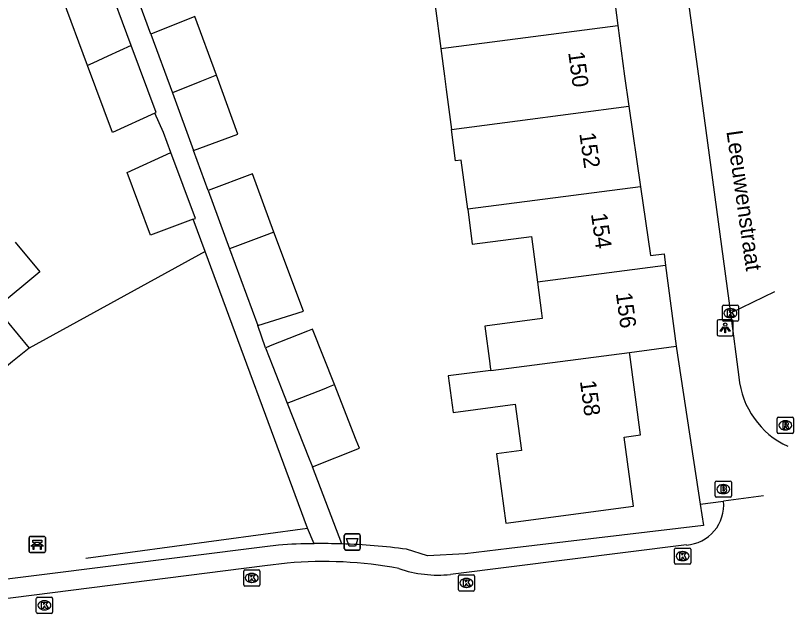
# Model space of a CAD drawing. Extents: x 163150 to 163546, y 380933 to 381635.
# Drawn here: x 163484.57 to 163532.74, y 380966.75 to 381003.76 of the extents above; entities that cross this region are included whole.
import ezdxf

# ---------------------------------------------------------------- set-up
doc = ezdxf.new("R2010")
doc.units = 0
for name, color, linetype in [('IMGEO_Afvalbak', 7, 'Continuous'), ('IMGEO_Bank', 7, 'Continuous'), ('IMGEO_Brandkraan', 7, 'Continuous'), ('IMGEO_Hek', 7, 'Continuous'), ('IMGEO_Kolk', 7, 'Continuous'), ('IMGEO_Lichtpunt', 7, 'Continuous'), ('IMGEO_Muur', 7, 'Continuous'), ('IMGEO_Openbare_ruimte_label', 7, 'Continuous'), ('IMGEO_Pand', 7, 'Continuous'), ('IMGEO_Pand_nummerreeks', 7, 'Continuous'), ('IMGEO_Rijbaan_lokaal_open', 7, 'Continuous'), ('IMGEO_Rioolput', 7, 'Continuous'), ('IMGEO_Voetpad_open', 7, 'Continuous')]:
    doc.layers.add(name, color=color, linetype=linetype)

msp = doc.modelspace()

# ---------------------------------------------------------------- linework, layer by layer
at = {"layer": 'IMGEO_Afvalbak'}
for p, q in [((163504.927, 380970.776), (163504.927, 380971.576)), ((163504.927, 380971.576), (163504.927, 380970.776)), ((163505.027, 380971.676), (163505.817, 380971.676)), ((163505.817, 380971.676), (163505.027, 380971.676)), ((163505.917, 380971.576), (163505.917, 380970.776)), ((163505.917, 380970.776), (163505.917, 380971.576)), ((163505.817, 380970.676), (163505.027, 380970.676)), ((163505.027, 380970.676), (163505.817, 380970.676))]:
    msp.add_line(p, q, dxfattribs=at)
msp.add_lwpolyline([(163505.07, 380971.39), (163505.774, 380971.39), (163505.625, 380970.92), (163505.219, 380970.92), (163505.07, 380971.39)], dxfattribs=at)
for centre, start, end in [((163505.027, 380971.576), 90, 180), ((163505.027, 380971.576), 90, 180), ((163505.817, 380971.576), 0, 90), ((163505.817, 380971.576), 360, 90), ((163505.027, 380970.776), 180, 270), ((163505.027, 380970.776), 180, 270), ((163505.817, 380970.776), 270, 0), ((163505.817, 380970.776), 270, 0)]:
    msp.add_arc(centre, 0.1, start, end, dxfattribs=at)
at = {"layer": 'IMGEO_Bank'}
for p, q in [((163485.487, 380971.517), (163486.328, 380971.517)), ((163486.328, 380971.517), (163485.487, 380971.517)), ((163485.412, 380970.592), (163485.412, 380971.433)), ((163485.412, 380971.433), (163485.412, 380970.592)), ((163485.721, 380971.023), (163485.721, 380971.129)), ((163485.765, 380971.129), (163485.765, 380971.023)), ((163486.053, 380971.135), (163485.771, 380971.135)), ((163485.771, 380971.017), (163486.053, 380971.017)), ((163486.059, 380971.023), (163486.059, 380971.129)), ((163486.103, 380971.129), (163486.103, 380971.023)), ((163486.412, 380971.442), (163486.412, 380970.601)), ((163486.412, 380970.601), (163486.412, 380971.442)), ((163486.109, 380970.915), (163485.716, 380970.915)), ((163486.337, 380970.517), (163485.496, 380970.517)), ((163485.496, 380970.517), (163486.337, 380970.517))]:
    msp.add_line(p, q, dxfattribs=at)
for points in [[(163485.659, 380970.915), (163485.517, 380970.915), (163485.629, 380971.017), (163485.715, 380971.017)], [(163485.715, 380971.135), (163485.629, 380971.135), (163485.629, 380971.296), (163486.192, 380971.296), (163486.192, 380971.135), (163486.109, 380971.135)], [(163486.109, 380971.017), (163486.192, 380971.017), (163486.304, 380970.915), (163486.165, 380970.915)], [(163485.709, 380970.908), (163485.709, 380970.701), (163485.666, 380970.701), (163485.666, 380970.908)], [(163486.159, 380970.908), (163486.159, 380970.701), (163486.115, 380970.701), (163486.115, 380970.908)]]:
    msp.add_lwpolyline(points, dxfattribs=at)
for centre, radius, start, end in [((163485.49, 380971.439), 0.0779, 92.4484, 184.2845), ((163485.49, 380971.439), 0.0779, 92.4484, 184.2845), ((163486.334, 380971.439), 0.0779, 2.4484, 94.2845), ((163486.334, 380971.439), 0.0779, 2.4484, 94.2845), ((163485.714, 380971.128), 0.00671, 2.8957, 87.1043), ((163485.714, 380971.024), 0.00671, 272.8957, 357.1043), ((163485.771, 380971.128), 0.00671, 92.8957, 177.1043), ((163485.771, 380971.024), 0.00671, 182.8957, 267.1043), ((163486.053, 380971.128), 0.00671, 2.8957, 87.1043), ((163486.053, 380971.024), 0.00671, 272.8957, 357.1043), ((163486.11, 380971.128), 0.00671, 92.8957, 177.1043), ((163486.11, 380971.024), 0.00671, 182.8957, 267.1043), ((163485.49, 380970.595), 0.0779, 182.4484, 274.2845), ((163485.49, 380970.595), 0.0779, 182.4484, 274.2845), ((163485.659, 380970.908), 0.00671, 2.8957, 87.1043), ((163485.716, 380970.908), 0.00671, 92.8957, 177.1043), ((163486.108, 380970.908), 0.00671, 2.8957, 87.1043), ((163486.165, 380970.908), 0.00671, 92.8957, 177.1043), ((163486.334, 380970.595), 0.0779, 272.4484, 4.2845), ((163486.334, 380970.595), 0.0779, 272.4484, 4.2845)]:
    msp.add_arc(centre, radius, start, end, dxfattribs=at)
at = {"layer": 'IMGEO_Brandkraan'}
for p, q in [((163527.898, 380974.021), (163527.898, 380974.873)), ((163527.973, 380974.947), (163528.825, 380974.947)), ((163528.899, 380974.873), (163528.899, 380974.021)), ((163528.386, 380974.727), (163528.411, 380974.727)), ((163528.825, 380973.947), (163527.973, 380973.947)), ((163528.409, 380974.167), (163528.384, 380974.167))]:
    msp.add_line(p, q, dxfattribs=at)
for points in [[(163527.898, 380974.021), (163527.898, 380974.873)], [(163527.973, 380974.947), (163528.825, 380974.947)], [(163528.899, 380974.873), (163528.899, 380974.021)], [(163528.246, 380974.647), (163528.246, 380974.247), (163528.459, 380974.247)], [(163528.477, 380974.647), (163528.246, 380974.647)], [(163528.425, 380974.566), (163528.371, 380974.566), (163528.371, 380974.49)], [(163528.371, 380974.49), (163528.424, 380974.49)], [(163528.433, 380974.414), (163528.371, 380974.414), (163528.371, 380974.333)], [(163528.825, 380973.947), (163527.973, 380973.947)], [(163528.371, 380974.333), (163528.433, 380974.333)]]:
    msp.add_lwpolyline(points, dxfattribs=at)
for centre, radius, start, end in [((163527.975, 380974.871), 0.0765, 91.552, 178.448), ((163527.975, 380974.871), 0.0765, 91.552, 178.448), ((163528.823, 380974.871), 0.0765, 1.552, 88.448), ((163528.823, 380974.871), 0.0765, 1.552, 88.448), ((163528.426, 380974.528), 0.0379, 267.8285, 90.9355), ((163528.434, 380974.373), 0.0404, 269.8759, 90.5077), ((163528.481, 380974.502), 0.145, 59.4692, 91.5367), ((163528.506, 380974.549), 0.0922, 285.5137, 58.1501), ((163528.511, 380974.357), 0.105, 301.3115, 78.989), ((163527.975, 380974.023), 0.0765, 181.552, 268.448), ((163527.975, 380974.023), 0.0765, 181.552, 268.448), ((163528.465, 380974.498), 0.251, 268.6676, 293.5347), ((163528.823, 380974.023), 0.0765, 271.552, 358.448), ((163528.823, 380974.023), 0.0765, 271.552, 358.448)]:
    msp.add_arc(centre, radius, start, end, dxfattribs=at)
for centre, major_axis, ratio, start_param, end_param in [((163528.385, 380974.447), (-0.387, 0.002), 0.722429, 4.712389, 7.853982), ((163528.41, 380974.447), (-0.39, 0.002), 0.717154, 1.570796, 4.712389)]:
    msp.add_ellipse(centre, major_axis=major_axis, ratio=ratio, start_param=start_param, end_param=end_param, dxfattribs=at)
at = {"layer": 'IMGEO_Hek'}
msp.add_lwpolyline([(163488.922, 380970.181), (163502.654, 380972.027), (163496.316, 380989.15), (163485.4, 380983.172)], dxfattribs=at)
at = {"layer": 'IMGEO_Kolk'}
for p, q in [((163528.339, 380984.912), (163528.339, 380985.764)), ((163528.414, 380985.838), (163529.266, 380985.838)), ((163528.827, 380985.618), (163528.852, 380985.618)), ((163529.34, 380985.764), (163529.34, 380984.912)), ((163528.85, 380985.058), (163528.825, 380985.058)), ((163529.266, 380984.838), (163528.414, 380984.838)), ((163525.38, 380969.874), (163525.38, 380970.726)), ((163525.455, 380970.8), (163526.307, 380970.8)), ((163525.868, 380970.58), (163525.893, 380970.58)), ((163526.381, 380970.726), (163526.381, 380969.874)), ((163526.307, 380969.8), (163525.455, 380969.8)), ((163525.891, 380970.02), (163525.866, 380970.02)), ((163498.696, 380968.523), (163498.696, 380969.375)), ((163498.771, 380969.449), (163499.623, 380969.449)), ((163499.184, 380969.229), (163499.209, 380969.229)), ((163499.697, 380969.375), (163499.697, 380968.523)), ((163512.065, 380969.14), (163512.917, 380969.14)), ((163499.207, 380968.669), (163499.182, 380968.669)), ((163511.99, 380968.214), (163511.99, 380969.066)), ((163512.478, 380968.92), (163512.503, 380968.92)), ((163512.991, 380969.066), (163512.991, 380968.214)), ((163499.623, 380968.449), (163498.771, 380968.449)), ((163512.917, 380968.14), (163512.065, 380968.14)), ((163512.501, 380968.36), (163512.476, 380968.36)), ((163485.854, 380966.827), (163485.854, 380967.679)), ((163485.929, 380967.753), (163486.781, 380967.753)), ((163486.855, 380967.679), (163486.855, 380966.827)), ((163486.342, 380967.533), (163486.367, 380967.533)), ((163486.781, 380966.753), (163485.929, 380966.753)), ((163486.365, 380966.973), (163486.34, 380966.973))]:
    msp.add_line(p, q, dxfattribs=at)
for points in [[(163528.339, 380984.912), (163528.339, 380985.764)], [(163528.414, 380985.838), (163529.266, 380985.838)], [(163528.66, 380985.538), (163528.783, 380985.538), (163528.783, 380985.387), (163528.913, 380985.538), (163529.077, 380985.538), (163528.931, 380985.387), (163529.084, 380985.138), (163528.932, 380985.138), (163528.847, 380985.302), (163528.783, 380985.235), (163528.783, 380985.138), (163528.66, 380985.138), (163528.66, 380985.538)], [(163529.34, 380985.764), (163529.34, 380984.912)], [(163529.266, 380984.838), (163528.414, 380984.838)], [(163525.38, 380969.874), (163525.38, 380970.726)], [(163525.455, 380970.8), (163526.307, 380970.8)], [(163526.381, 380970.726), (163526.381, 380969.874)], [(163525.701, 380970.5), (163525.824, 380970.5), (163525.824, 380970.349), (163525.954, 380970.5), (163526.118, 380970.5), (163525.972, 380970.349), (163526.125, 380970.1), (163525.973, 380970.1), (163525.888, 380970.264), (163525.824, 380970.197), (163525.824, 380970.1), (163525.701, 380970.1), (163525.701, 380970.5)], [(163526.307, 380969.8), (163525.455, 380969.8)], [(163498.696, 380968.523), (163498.696, 380969.375)], [(163498.771, 380969.449), (163499.623, 380969.449)], [(163499.017, 380969.149), (163499.14, 380969.149), (163499.14, 380968.998), (163499.27, 380969.149), (163499.434, 380969.149), (163499.288, 380968.998), (163499.441, 380968.749), (163499.289, 380968.749), (163499.204, 380968.913), (163499.14, 380968.846), (163499.14, 380968.749), (163499.017, 380968.749), (163499.017, 380969.149)], [(163499.697, 380969.375), (163499.697, 380968.523)], [(163512.065, 380969.14), (163512.917, 380969.14)], [(163511.99, 380968.214), (163511.99, 380969.066)], [(163512.311, 380968.84), (163512.434, 380968.84), (163512.434, 380968.689), (163512.564, 380968.84), (163512.728, 380968.84), (163512.582, 380968.689), (163512.735, 380968.44), (163512.583, 380968.44), (163512.498, 380968.604), (163512.434, 380968.537), (163512.434, 380968.44), (163512.311, 380968.44), (163512.311, 380968.84)], [(163512.991, 380969.066), (163512.991, 380968.214)], [(163499.623, 380968.449), (163498.771, 380968.449)], [(163512.917, 380968.14), (163512.065, 380968.14)], [(163485.854, 380966.827), (163485.854, 380967.679)], [(163485.929, 380967.753), (163486.781, 380967.753)], [(163486.855, 380967.679), (163486.855, 380966.827)], [(163486.175, 380967.453), (163486.298, 380967.453), (163486.298, 380967.302), (163486.428, 380967.453), (163486.592, 380967.453), (163486.446, 380967.302), (163486.599, 380967.053), (163486.447, 380967.053), (163486.362, 380967.217), (163486.298, 380967.15), (163486.298, 380967.053), (163486.175, 380967.053), (163486.175, 380967.453)], [(163486.781, 380966.753), (163485.929, 380966.753)]]:
    msp.add_lwpolyline(points, dxfattribs=at)
for centre, start, end in [((163528.416, 380985.762), 91.552, 178.448), ((163528.416, 380985.762), 91.552, 178.448), ((163529.264, 380985.762), 1.552, 88.448), ((163529.264, 380985.762), 1.552, 88.448), ((163528.416, 380984.914), 181.552, 268.448), ((163528.416, 380984.914), 181.552, 268.448), ((163529.264, 380984.914), 271.552, 358.448), ((163529.264, 380984.914), 271.552, 358.448), ((163525.457, 380970.724), 91.552, 178.448), ((163525.457, 380970.724), 91.552, 178.448), ((163526.305, 380970.724), 1.552, 88.448), ((163526.305, 380970.724), 1.552, 88.448), ((163525.457, 380969.876), 181.552, 268.448), ((163525.457, 380969.876), 181.552, 268.448), ((163526.305, 380969.876), 271.552, 358.448), ((163526.305, 380969.876), 271.552, 358.448), ((163498.773, 380969.373), 91.552, 178.448), ((163498.773, 380969.373), 91.552, 178.448), ((163499.621, 380969.373), 1.552, 88.448), ((163499.621, 380969.373), 1.552, 88.448), ((163512.067, 380969.064), 91.552, 178.448), ((163512.067, 380969.064), 91.552, 178.448), ((163512.915, 380969.064), 1.552, 88.448), ((163512.915, 380969.064), 1.552, 88.448), ((163498.773, 380968.525), 181.552, 268.448), ((163498.773, 380968.525), 181.552, 268.448), ((163499.621, 380968.525), 271.552, 358.448), ((163499.621, 380968.525), 271.552, 358.448), ((163512.067, 380968.216), 181.552, 268.448), ((163512.067, 380968.216), 181.552, 268.448), ((163512.915, 380968.216), 271.552, 358.448), ((163512.915, 380968.216), 271.552, 358.448), ((163485.931, 380967.677), 91.552, 178.448), ((163485.931, 380967.677), 91.552, 178.448), ((163486.779, 380967.677), 1.552, 88.448), ((163486.779, 380967.677), 1.552, 88.448), ((163485.931, 380966.829), 181.552, 268.448), ((163485.931, 380966.829), 181.552, 268.448), ((163486.779, 380966.829), 271.552, 358.448), ((163486.779, 380966.829), 271.552, 358.448)]:
    msp.add_arc(centre, 0.0765, start, end, dxfattribs=at)
for centre, major_axis, ratio, start_param, end_param in [((163528.826, 380985.338), (-0.387, 0.002), 0.722429, 4.712389, 7.853982), ((163528.851, 380985.338), (-0.39, 0.002), 0.717154, 1.570796, 4.712389), ((163525.867, 380970.3), (-0.387, 0.002), 0.722429, 4.712389, 7.853982), ((163525.892, 380970.3), (-0.39, 0.002), 0.717154, 1.570796, 4.712389), ((163499.183, 380968.949), (-0.387, 0.002), 0.722429, 4.712389, 7.853982), ((163499.208, 380968.949), (-0.39, 0.002), 0.717154, 1.570796, 4.712389), ((163512.477, 380968.64), (-0.387, 0.002), 0.722429, 4.712389, 7.853982), ((163512.502, 380968.64), (-0.39, 0.002), 0.717154, 1.570796, 4.712389), ((163486.341, 380967.253), (-0.387, 0.002), 0.722429, 4.712389, 7.853982), ((163486.366, 380967.253), (-0.39, 0.002), 0.717154, 1.570796, 4.712389)]:
    msp.add_ellipse(centre, major_axis=major_axis, ratio=ratio, start_param=start_param, end_param=end_param, dxfattribs=at)
at = {"layer": 'IMGEO_Lichtpunt'}
for p, q in [((163528.018, 380984.831), (163528.018, 380984.024)), ((163528.018, 380984.831), (163528.018, 380984.024)), ((163528.92, 380984.926), (163528.112, 380984.926)), ((163528.92, 380984.926), (163528.112, 380984.926)), ((163529.014, 380984.024), (163529.014, 380984.831)), ((163529.014, 380984.024), (163529.014, 380984.831)), ((163528.112, 380983.93), (163528.92, 380983.93)), ((163528.112, 380983.93), (163528.92, 380983.93))]:
    msp.add_line(p, q, dxfattribs=at)
for points in [[(163528.392, 380984.495), (163528.431, 380984.467), (163528.243, 380984.205), (163528.205, 380984.232), (163528.392, 380984.495)], [(163528.604, 380984.467), (163528.642, 380984.494), (163528.829, 380984.232), (163528.79, 380984.204), (163528.604, 380984.467)], [(163528.494, 380984.447), (163528.541, 380984.447), (163528.541, 380984.125), (163528.494, 380984.125), (163528.494, 380984.447)]]:
    msp.add_lwpolyline(points, dxfattribs=at)
msp.add_circle((163528.517, 380984.629), 0.0994, dxfattribs=at)
for centre, start, end in [((163528.112, 380984.831), 90, 180), ((163528.112, 380984.831), 90, 180), ((163528.92, 380984.831), 0, 90), ((163528.92, 380984.831), 0, 90), ((163528.112, 380984.024), 180, 270), ((163528.112, 380984.024), 180, 270), ((163528.92, 380984.024), 270, 0), ((163528.92, 380984.024), 270, 360)]:
    msp.add_arc(centre, 0.0946, start, end, dxfattribs=at)
at = {"layer": 'IMGEO_Muur'}
msp.add_lwpolyline([(163515.137, 380970.763), (163512.403, 380970.436), (163510.086, 380970.31)], dxfattribs=at)
at = {"layer": 'IMGEO_Pand'}
for points in [[(163521.22, 381008.132), (163521.873, 381003.137)], [(163514.228, 381007.221), (163514.534, 381004.874), (163510.563, 381004.356), (163510.908, 381001.708)], [(163489.023, 381000.659), (163487.468, 381004.845), (163490.173, 381006.093)], [(163491.729, 381001.907), (163490.173, 381006.093)], [(163497.004, 381000.057), (163495.67, 381003.69), (163492.949, 381002.608)], [(163510.908, 381001.708), (163521.873, 381003.137)], [(163521.873, 381003.137), (163522.282, 381000), (163522.55, 380998.146)], [(163492.949, 381002.608), (163494.282, 380998.975)], [(163491.729, 381001.907), (163490.283, 381001.241), (163489.356, 381000.813), (163489.023, 381000.659)], [(163493.185, 380997.725), (163493.269, 380997.763), (163491.729, 381001.907)], [(163510.908, 381001.708), (163511.131, 381000), (163511.239, 380999.172), (163511.56, 380996.713)], [(163493.185, 380997.725), (163490.562, 380996.515), (163489.023, 381000.659)], [(163497.004, 381000.057), (163496.401, 380999.817), (163495.985, 380999.652), (163494.282, 380998.975)], [(163495.595, 380995.399), (163498.337, 380996.424), (163497.004, 381000.057)], [(163494.282, 380998.975), (163495.595, 380995.399)], [(163511.56, 380996.713), (163515.647, 380997.246), (163522.55, 380998.146)], [(163522.55, 380998.146), (163523.27, 380993.16)], [(163512.567, 380991.764), (163512.164, 380994.81), (163511.814, 380994.764), (163511.56, 380996.713)], [(163495.572, 380991.155), (163492.92, 380990.17), (163491.484, 380994.034), (163494.19, 380995.282)], [(163495.572, 380991.155), (163495.705, 380991.204), (163494.19, 380995.282)], [(163500.568, 380990.348), (163499.242, 380993.958), (163496.5, 380992.933)], [(163496.5, 380992.933), (163497.825, 380989.321)], [(163523.27, 380993.16), (163512.567, 380991.764)], [(163523.27, 380993.16), (163523.884, 380988.904), (163524.727, 380989.016), (163524.824, 380988.283)], [(163512.567, 380991.764), (163512.854, 380989.599), (163516.511, 380990.084), (163516.887, 380987.248)], [(163500.568, 380990.348), (163499.96, 380990.12), (163497.825, 380989.321)], [(163499.565, 380984.58), (163502.401, 380985.45), (163500.568, 380990.348)], [(163484.546, 380989.732), (163486.067, 380987.888), (163483.355, 380985.651), (163485.4, 380983.172), (163484.386, 380982.336), (163483.867, 380981.908), (163479.391, 380978.216), (163478.766, 380977.7), (163475.211, 380981.981)], [(163497.825, 380989.321), (163499.565, 380984.58)], [(163524.824, 380988.283), (163516.887, 380987.248)], [(163524.824, 380988.283), (163525.486, 380983.29)], [(163516.887, 380987.248), (163517.141, 380985.338), (163517.186, 380984.999), (163513.63, 380984.528), (163513.936, 380982.217), (163513.964, 380982.002), (163513.992, 380981.791)], [(163504.313, 380980.912), (163502.958, 380984.345), (163502.655, 380984.225), (163500.329, 380983.306), (163500.219, 380983.263), (163500.042, 380983.193)], [(163500.042, 380983.193), (163500.497, 380982.04), (163501.397, 380979.76)], [(163522.588, 380982.912), (163525.486, 380983.29)], [(163513.992, 380981.791), (163511.366, 380981.448), (163511.665, 380979.192), (163515.518, 380979.703), (163515.897, 380976.842), (163514.358, 380976.638), (163514.928, 380972.34), (163522.829, 380973.387), (163522.262, 380977.665), (163523.266, 380977.798), (163522.607, 380982.769), (163522.588, 380982.912)], [(163513.992, 380981.791), (163522.588, 380982.912)], [(163501.397, 380979.76), (163503.572, 380980.619), (163503.833, 380980.722), (163504.01, 380980.792), (163504.313, 380980.912)], [(163502.953, 380975.82), (163505.869, 380976.971), (163505.668, 380977.479), (163504.313, 380980.912)], [(163501.397, 380979.76), (163502.752, 380976.328), (163502.953, 380975.82)]]:
    msp.add_lwpolyline(points, dxfattribs=at)
at = {"layer": 'IMGEO_Rijbaan_lokaal_open'}
for points in [[(163515.38, 381086.08), (163515.628, 381083.882), (163517.691, 381068.556), (163520.526, 381047.354), (163523.013, 381028.635), (163525.88, 381007.238), (163526.859, 381000), (163528.841, 380985.339)], [(163531.562, 380986.655), (163528.841, 380985.339)], [(163528.841, 380985.339), (163529.362, 380981.369)]]:
    msp.add_lwpolyline(points, dxfattribs=at)
msp.add_arc((163534.606, 380981.879), 5.268, 185.559, 245.1192, dxfattribs=at)
at = {"layer": 'IMGEO_Rioolput'}
for p, q in [((163531.741, 380977.969), (163531.741, 380978.821)), ((163531.816, 380978.895), (163532.668, 380978.895)), ((163532.742, 380978.821), (163532.742, 380977.969)), ((163532.229, 380978.675), (163532.254, 380978.675)), ((163532.668, 380977.895), (163531.816, 380977.895)), ((163532.252, 380978.115), (163532.227, 380978.115))]:
    msp.add_line(p, q, dxfattribs=at)
for points in [[(163531.741, 380977.969), (163531.741, 380978.821)], [(163531.816, 380978.895), (163532.668, 380978.895)], [(163532.742, 380978.821), (163532.742, 380977.969)], [(163532.33, 380978.593), (163532.078, 380978.595), (163532.078, 380978.195)], [(163532.078, 380978.195), (163532.202, 380978.195), (163532.202, 380978.357), (163532.213, 380978.357)], [(163532.256, 380978.514), (163532.202, 380978.514), (163532.202, 380978.433)], [(163532.202, 380978.433), (163532.254, 380978.433)], [(163532.26, 380978.328), (163532.331, 380978.195), (163532.471, 380978.195), (163532.406, 380978.321)], [(163532.668, 380977.895), (163531.816, 380977.895)]]:
    msp.add_lwpolyline(points, dxfattribs=at)
for centre, radius, start, end in [((163531.818, 380978.819), 0.0765, 91.552, 178.448), ((163531.818, 380978.819), 0.0765, 91.552, 178.448), ((163532.666, 380978.819), 0.0765, 1.552, 88.448), ((163532.666, 380978.819), 0.0765, 1.552, 88.448), ((163532.212, 380978.304), 0.0533, 26.0293, 88.6989), ((163532.238, 380978.622), 0.19, 274.7715, 282.9687), ((163532.262, 380978.418), 0.0964, 77.0061, 93.1865), ((163532.276, 380978.475), 0.0378, 276.6634, 79.6772), ((163532.329, 380978.483), 0.109, 350.3612, 89.416), ((163532.327, 380978.483), 0.112, 277.5842, 350.9817), ((163532.311, 380978.268), 0.108, 29.5134, 73.7905), ((163531.818, 380977.971), 0.0765, 181.552, 268.448), ((163531.818, 380977.971), 0.0765, 181.552, 268.448), ((163532.666, 380977.971), 0.0765, 271.552, 358.448), ((163532.666, 380977.971), 0.0765, 271.552, 358.448)]:
    msp.add_arc(centre, radius, start, end, dxfattribs=at)
for centre, major_axis, ratio, start_param, end_param in [((163532.228, 380978.395), (-0.387, 0.002), 0.722429, 4.712389, 7.853982), ((163532.253, 380978.395), (-0.39, 0.002), 0.717154, 1.570796, 4.712389)]:
    msp.add_ellipse(centre, major_axis=major_axis, ratio=ratio, start_param=start_param, end_param=end_param, dxfattribs=at)
at = {"layer": 'IMGEO_Voetpad_open'}
for points in [[(163500.852, 380970.985), (163500, 380970.878), (163481.073, 380968.493), (163480.619, 380969.042), (163477.178, 380973.206), (163475.613, 380975.099), (163455.037, 381000), (163446.308, 381010.353), (163442.086, 381015.361), (163437.58, 381020.705)], [(163492.949, 381002.608), (163492.055, 381005.043)], [(163494.19, 380995.282), (163493.731, 380996.518), (163493.185, 380997.725)], [(163496.5, 380992.933), (163495.595, 380995.399)], [(163503.057, 380971.07), (163502.654, 380972.027), (163496.316, 380989.15), (163495.572, 380991.155)], [(163500.042, 380983.193), (163499.565, 380984.58)], [(163525.486, 380983.29), (163525.504, 380983.153), (163526.975, 380973.515)], [(163504.778, 380971.051), (163502.953, 380975.82)], [(163530.89, 380974.03), (163530.89, 380974.03), (163528.416, 380973.702)], [(163526.975, 380973.515), (163527.167, 380972.2), (163515.137, 380970.763), (163512.403, 380970.436), (163510.086, 380970.31), (163508.778, 380970.721)], [(163526.975, 380973.515), (163528.416, 380973.702)], [(163526.122, 380970.988), (163511.505, 380969.166)], [(163501.379, 380969.865), (163500, 380969.691), (163480.83, 380967.261), (163475.361, 380968.436)]]:
    msp.add_lwpolyline(points, dxfattribs=at)
for centre, radius, start, end in [((163525.948, 380973.461), 2.48, 274.0212, 5.5667), ((163503.466, 380931.816), 39.256, 90.597, 93.8181), ((163503.488, 380932.112), 38.961, 88.1018, 90.6331), ((163504.043, 380937.731), 33.328, 81.8317, 88.7359), ((163503.642, 380944.85), 25.117, 79.3064, 95.1702), ((163510.726, 380976.563), 7.438, 250.9854, 276.0083)]:
    msp.add_arc(centre, radius, start, end, dxfattribs=at)

# ---------------------------------------------------------------- texts
at = {"layer": 'IMGEO_Openbare_ruimte_label'}
msp.add_text('Leeuwenstraat', height=1, rotation=278.0491, dxfattribs=at).set_placement((163528.59, 380996.586))
at = {"layer": 'IMGEO_Pand_nummerreeks'}
for s, rotation, p in [('150', 277.7134, (163518.79, 381001.474)), ('152', 278.223, (163519.479, 380996.459)), ('154', 278.2154, (163520.199, 380991.473)), ('156', 277.5514, (163521.743, 380986.563)), ('158', 277.5514, (163519.517, 380981.124))]:
    msp.add_text(s, height=1, rotation=rotation, dxfattribs=at).set_placement(p)

doc.saveas('drawing.dxf')
